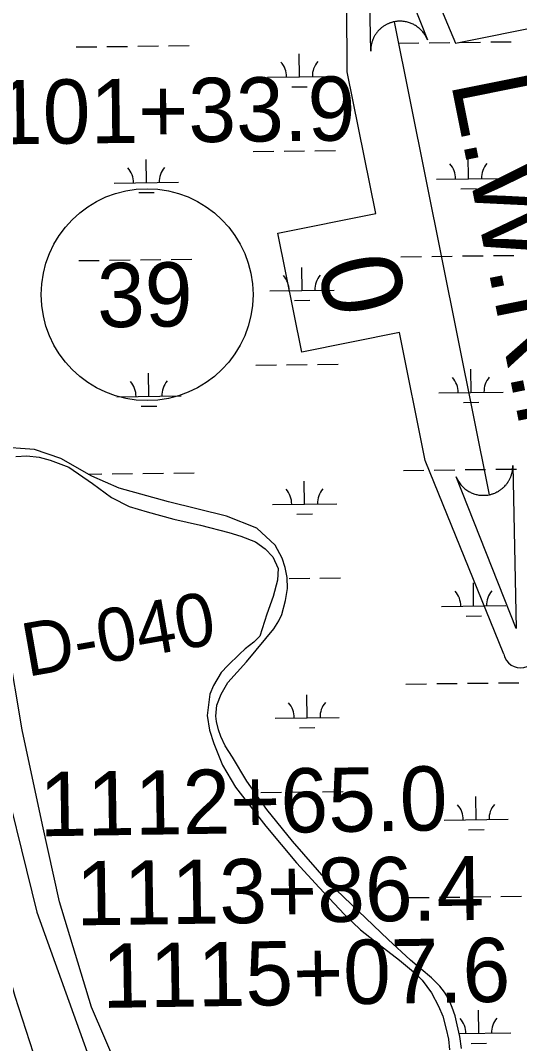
# Model space of a CAD drawing. Extents: x 3694830 to 3732949, y 415201 to 440970.
# Drawn here: x 3719230 to 3720008, y 422124 to 423717 of the extents above; entities that cross this region are included whole.
import ezdxf

# ---------------------------------------------------------------- set-up
doc = ezdxf.new("R2010")
doc.units = 0
for name, color, linetype in [('V-LEVE-TOET', 7, 'Continuous'), ('V-RIVR-EDGE', 7, 'Continuous'), ('V-RIVR-RANG-IDEN', 7, 'Continuous'), ('V-ROAD-CNTR', 7, 'Continuous'), ('V-ROAD-IDEN', 7, 'Continuous'), ('V-SITE-VEGE', 7, 'Continuous'), ('V-SURV-IDEN', 7, 'Continuous'), ('V-TOPO-WATR-IDEN', 7, 'Continuous'), ('V-WETL-SWMP', 7, 'Continuous')]:
    doc.layers.add(name, color=color, linetype=linetype)

msp = doc.modelspace()

# ---------------------------------------------------------------- linework, layer by layer
at = {"layer": 'V-LEVE-TOET'}
msp.add_lwpolyline([(3719250.8, 422108.8), (3719222.3, 422197), (3719194.8, 422291.7), (3719180.7, 422352.4), (3719172.6, 422421.2), (3719168.1, 422469.1), (3719160.3, 422512), (3719146.7, 422581.8), (3719133.4, 422653.2), (3719118.2, 422780.4)], dxfattribs=at)
at = {"layer": 'V-RIVR-EDGE'}
msp.add_spline([(3719087.8, 422149.1), (3719100.4, 422102), (3719125.5, 422030.5), (3719143.5, 421974.4), (3719160.1, 421927.3), (3719171.7, 421879.4), (3719179.4, 421857.6), (3719191.1, 421841.3), (3719203.2, 421812.4), (3719211.7, 421786.1), (3719228.4, 421748.1), (3719249.5, 421687.5), (3719275.5, 421623.6), (3719294.9, 421574.3), (3719319.2, 421529.5), (3719344.8, 421485.6), (3719365.1, 421454.3), (3719388.1, 421409), (3719408.3, 421361.5), (3719431.6, 421299.1), (3719443.8, 421266.9), (3719451.8, 421214.5), (3719458, 421174.7), (3719470.6, 421133), (3719483.6, 421095.5), (3719507.4, 421024.4), (3719533, 420955.6), (3719560.9, 420891.8), (3719570.8, 420861)], degree=3, dxfattribs=at)
at = {"layer": 'V-ROAD-CNTR'}
msp.add_lwpolyline([(3718947.5, 424793.9), (3718964, 424411.4), (3718982.2, 424062.3), (3719015.2, 423758.3), (3719087.3, 423283.5), (3719154, 422831.8), (3719191.5, 422587.8), (3719255.9, 422328.3), (3719350.6, 422063.9), (3719444.2, 421874.4), (3719568.8, 421676.5), (3719728.1, 421465.7), (3719881.2, 421306.9), (3720024.6, 421178.6), (3720151.9, 421084.4), (3720292.9, 420993.4), (3720460.7, 420905.9), (3720538.9, 420876)], dxfattribs=at)
at = {"layer": 'V-ROAD-IDEN'}
msp.add_circle((3719427.6, 423289.7), 165, dxfattribs=at)
msp.add_circle((3719427.6, 423289.7), 165, dxfattribs=at)
at = {"layer": 'V-SITE-VEGE'}
for p, q in [((3719223.3, 423037.5), (3719240.3, 423038.7)), ((3719240.3, 423038.7), (3719259.2, 423036.7)), ((3719259.2, 423036.7), (3719276.6, 423031.9)), ((3719276.6, 423031.9), (3719305.5, 423020.9)), ((3719305.5, 423020.9), (3719342.6, 422995.6)), ((3719342.6, 422995.6), (3719371.9, 422973.8)), ((3719371.9, 422973.8), (3719399.6, 422959.6)), ((3719399.6, 422959.6), (3719427.6, 422951.6)), ((3719427.6, 422951.6), (3719469.1, 422940.2)), ((3719469.1, 422940.2), (3719511, 422930.7)), ((3719511, 422930.7), (3719554.9, 422919.2)), ((3719554.9, 422919.2), (3719573.5, 422913.6)), ((3719573.5, 422913.6), (3719596.4, 422904.9)), ((3719596.4, 422904.9), (3719611.4, 422893.9)), ((3719611.4, 422893.9), (3719623.7, 422881.6)), ((3719623.7, 422881.6), (3719631.6, 422863.4)), ((3719631.6, 422863.4), (3719630.8, 422845.2)), ((3719630.8, 422845.2), (3719624.1, 422819.9)), ((3719624.1, 422819.9), (3719614.2, 422792.3)), ((3719614.2, 422792.3), (3719603.1, 422757.9)), ((3719603.1, 422757.9), (3719594, 422748.8)), ((3719232.7, 422612.2), (3719210.4, 422744.9)), ((3719594, 422748.8), (3719580.6, 422738.1)), ((3719571.5, 422730), (3719553.3, 422712.4)), ((3719580.6, 422738.1), (3719571.5, 422730)), ((3719553.3, 422712.4), (3719543.1, 422701.1)), ((3719543.1, 422701.1), (3719530.8, 422681.3)), ((3719530.8, 422681.3), (3719525.4, 422667.4)), ((3719525.4, 422667.4), (3719521.1, 422634.2)), ((3719521.1, 422634.2), (3719524.9, 422611.6)), ((3719264.6, 422464), (3719232.7, 422612.2)), ((3719524.9, 422611.6), (3719531.3, 422590.8)), ((3719531.3, 422590.8), (3719545.2, 422557)), ((3719545.2, 422557), (3719565.1, 422522.7)), ((3719565.1, 422522.7), (3719612.7, 422462.2)), ((3719291.2, 422344.3), (3719264.6, 422464)), ((3719612.7, 422462.2), (3719660.4, 422404.8)), ((3719660.4, 422404.8), (3719695.8, 422366.3)), ((3719695.8, 422366.3), (3719734.9, 422324.5)), ((3719341, 422180.3), (3719291.2, 422344.3)), ((3719734.9, 422324.5), (3719760, 422300.9)), ((3719760, 422300.9), (3719789, 422277.9)), ((3719789, 422277.9), (3719820.6, 422253.2)), ((3719820.6, 422253.2), (3719842.5, 422235)), ((3719842.5, 422235), (3719855.9, 422222.1)), ((3719855.9, 422222.1), (3719870.9, 422202.3)), ((3719870.9, 422202.3), (3719881.6, 422182)), ((3719390.5, 422065.8), (3719341, 422180.3)), ((3719881.6, 422182), (3719888.1, 422166.4)), ((3719888.1, 422166.4), (3719893.4, 422146.1)), ((3719893.4, 422146.1), (3719897.2, 422130.5)), ((3719897.2, 422130.5), (3719898.8, 422113.9))]:
    msp.add_line(p, q, dxfattribs=at)
at = {"layer": 'V-TOPO-WATR-IDEN'}
msp.add_line((3719812.7, 423714.6), (3719960.6, 422978.1), dxfattribs=at)
for points in [[(3719983.4, 422729.8), (3719860.9, 423031.4), (3719820.9, 423230.8), (3719668.6, 423200.3), (3719631.4, 423385.6), (3719783.7, 423416.2), (3719739.4, 423636.7), (3719737.9, 423952.5)], [(3719789.9, 423962.9), (3719908.3, 423681.4), (3720050.2, 423709.9), (3720175.9, 423083.8), (3720034, 423055.3), (3720035.4, 422740.2)]]:
    msp.add_lwpolyline(points, dxfattribs=at)
for points in [[(3719776, 423669), (3719770.9, 423922.8), (3719864.2, 423686.7), (3719862.3, 423690.8), (3719860.1, 423694.6), (3719859.1, 423696.1), (3719858.2, 423697.4), (3719857, 423698.9), (3719855.8, 423700.3), (3719854.7, 423701.4), (3719853.2, 423702.9), (3719851.5, 423704.5), (3719850.5, 423705.3), (3719849.1, 423706.4), (3719847.3, 423707.7), (3719845.9, 423708.6), (3719844.3, 423709.5), (3719843.2, 423710.1), (3719842, 423710.7), (3719840.5, 423711.4), (3719839.2, 423712), (3719837.8, 423712.6), (3719836.6, 423713), (3719834.9, 423713.6), (3719833.2, 423714), (3719831.8, 423714.4), (3719830.2, 423714.7), (3719828.8, 423714.9), (3719827.5, 423715.1), (3719826.5, 423715.2), (3719825, 423715.4), (3719823.5, 423715.5), (3719822, 423715.5), (3719820.5, 423715.5), (3719819.2, 423715.4), (3719817.6, 423715.3), (3719816.4, 423715.2), (3719814.7, 423714.9), (3719812.7, 423714.6), (3719812.1, 423714.5), (3719811.2, 423714.3), (3719810.1, 423714), (3719809.1, 423713.7), (3719808.1, 423713.4), (3719807.1, 423713.1), (3719806, 423712.7), (3719805.2, 423712.4), (3719804.1, 423712), (3719803.1, 423711.5), (3719802.4, 423711.2), (3719800.5, 423710.3), (3719799.6, 423709.8), (3719798.9, 423709.4), (3719797.9, 423708.8), (3719797, 423708.2), (3719796, 423707.6), (3719794.9, 423706.8), (3719793.9, 423706.1), (3719793.1, 423705.5), (3719792.5, 423704.9), (3719791.6, 423704.2), (3719790.8, 423703.5), (3719790, 423702.7), (3719789.1, 423701.8), (3719788.3, 423701), (3719787.2, 423699.8), (3719786.5, 423699), (3719785.7, 423698), (3719785, 423697), (3719784.4, 423696.3), (3719783.8, 423695.4), (3719783, 423694.1), (3719782.9, 423694), (3719782.4, 423693.2), (3719782.1, 423692.6), (3719781.6, 423691.7), (3719781, 423690.6), (3719780.5, 423689.7), (3719780.1, 423688.8), (3719779.7, 423687.8), (3719779.2, 423686.7), (3719778.9, 423686), (3719778.6, 423685), (3719778.1, 423683.6), (3719777.9, 423682.7), (3719777.7, 423682.1), (3719777.5, 423681.5), (3719777.3, 423680.8), (3719777.1, 423679.8), (3719776.9, 423678.9), (3719776.7, 423677.9), (3719776.5, 423677), (3719776.4, 423675.7), (3719776.3, 423675), (3719776.1, 423673.8), (3719776, 423672.4), (3719776, 423671.4), (3719776, 423670.6), (3719776, 423669.9), (3719776, 423669.3)], [(3719997.3, 423023.7), (3720002.4, 422769.8), (3719909.1, 423006), (3719911, 423001.9), (3719913.2, 422998), (3719914.2, 422996.6), (3719915.1, 422995.3), (3719916.3, 422993.8), (3719917.5, 422992.4), (3719918.5, 422991.3), (3719920.1, 422989.7), (3719921.8, 422988.2), (3719922.8, 422987.4), (3719924.1, 422986.3), (3719925.9, 422985), (3719927.4, 422984.1), (3719929, 422983.2), (3719930, 422982.6), (3719931.2, 422982), (3719932.7, 422981.3), (3719934.1, 422980.7), (3719935.5, 422980.1), (3719936.7, 422979.7), (3719938.4, 422979.1), (3719940.1, 422978.7), (3719941.5, 422978.3), (3719943.1, 422978), (3719944.5, 422977.7), (3719945.7, 422977.6), (3719946.7, 422977.5), (3719948.2, 422977.3), (3719949.8, 422977.2), (3719951.2, 422977.2), (3719952.7, 422977.2), (3719954.1, 422977.3), (3719955.6, 422977.4), (3719956.9, 422977.5), (3719958.6, 422977.7), (3719960.6, 422978.1), (3719961.2, 422978.2), (3719962.1, 422978.4), (3719963.2, 422978.7), (3719964.2, 422979), (3719965.2, 422979.3), (3719966.1, 422979.6), (3719967.3, 422980), (3719968, 422980.3), (3719969.2, 422980.7), (3719970.2, 422981.2), (3719970.9, 422981.5), (3719972.7, 422982.4), (3719973.7, 422982.9), (3719974.3, 422983.3), (3719975.4, 422983.9), (3719976.3, 422984.5), (3719977.3, 422985.1), (3719978.4, 422985.9), (3719979.4, 422986.6), (3719980.1, 422987.2), (3719980.8, 422987.8), (3719981.7, 422988.5), (3719982.4, 422989.2), (3719983.3, 422990), (3719984.2, 422990.9), (3719985, 422991.7), (3719986, 422992.9), (3719986.8, 422993.7), (3719987.5, 422994.7), (3719988.3, 422995.6), (3719988.8, 422996.4), (3719989.4, 422997.3), (3719990.3, 422998.6), (3719990.3, 422998.7), (3719990.8, 422999.5), (3719991.2, 423000.1), (3719991.7, 423001), (3719992.3, 423002.1), (3719992.7, 423003), (3719993.1, 423003.8), (3719993.6, 423004.9), (3719994, 423006), (3719994.3, 423006.7), (3719994.7, 423007.7), (3719995.2, 423009.1), (3719995.4, 423009.9), (3719995.6, 423010.6), (3719995.8, 423011.2), (3719996, 423011.9), (3719996.2, 423012.9), (3719996.4, 423013.8), (3719996.6, 423014.8), (3719996.7, 423015.7), (3719996.9, 423017), (3719997, 423017.7), (3719997.1, 423018.9), (3719997.2, 423020.3), (3719997.3, 423021.3), (3719997.3, 423022.1), (3719997.3, 423022.8), (3719997.3, 423023.3)]]:
    msp.add_lwpolyline(points, close=True, dxfattribs=at)
msp.add_arc((3720009.4, 422735), 26.5, 191.3511, 11.3511, dxfattribs=at)
at = {"layer": 'V-WETL-SWMP'}
for p, q in [((3719819, 423681.4), (3719851, 423681.8)), ((3719867, 423681.9), (3719899, 423682.3)), ((3719915, 423682.5), (3719947, 423682.9)), ((3719963, 423683.1), (3719995, 423683.5)), ((3719317.1, 423675.4), (3719349.1, 423675.8)), ((3719365.1, 423676), (3719397.1, 423676.3)), ((3719413.1, 423676.5), (3719445.1, 423676.9)), ((3719461.1, 423677.1), (3719493.1, 423677.5)), ((3719665, 423628.8), (3719664.6, 423664.8)), ((3719615, 423628.2), (3719715, 423629.4)), ((3719653.2, 423613.2), (3719677.2, 423613.5)), ((3719593, 423512.5), (3719625, 423512.9)), ((3719641, 423513.1), (3719673, 423513.4)), ((3719689, 423513.6), (3719721, 423514)), ((3719928.4, 423470.1), (3719927.9, 423506.1)), ((3719426.5, 423464.1), (3719426.1, 423500.1)), ((3719376.5, 423463.5), (3719476.5, 423464.7)), ((3719878.4, 423469.5), (3719978.4, 423470.7)), ((3719414.7, 423448.5), (3719438.7, 423448.8)), ((3719916.6, 423454.5), (3719940.6, 423454.8)), ((3719823, 423348.7), (3719855, 423349.1)), ((3719871, 423349.3), (3719903, 423349.7)), ((3719919, 423349.9), (3719951, 423350.3)), ((3719967, 423350.4), (3719999, 423350.8)), ((3719321.1, 423342.7), (3719353.1, 423343.1)), ((3719369.1, 423343.3), (3719401.1, 423343.7)), ((3719417.1, 423343.9), (3719449.1, 423344.3)), ((3719465.1, 423344.5), (3719497.1, 423344.8)), ((3719669, 423296.1), (3719668.6, 423332.1)), ((3719619, 423295.5), (3719719, 423296.7)), ((3719657.2, 423280.6), (3719681.2, 423280.9)), ((3719597, 423179.8), (3719629, 423180.2)), ((3719645, 423180.4), (3719677, 423180.8)), ((3719693, 423181), (3719725, 423181.4)), ((3719932.3, 423137.4), (3719931.9, 423173.4)), ((3719430.5, 423131.4), (3719430, 423167.4)), ((3719380.5, 423130.8), (3719480.5, 423132)), ((3719882.3, 423136.8), (3719982.3, 423138)), ((3719418.6, 423115.9), (3719442.6, 423116.1)), ((3719920.5, 423121.8), (3719944.5, 423122.1)), ((3719252.4, 423048.6), (3719192.3, 423052.9)), ((3719293.1, 423034.3), (3719252.4, 423048.6)), ((3719341.3, 423007), (3719293.1, 423034.3)), ((3719469, 423011.8), (3719501, 423012.2)), ((3719826.9, 423016.1), (3719858.9, 423016.5)), ((3719874.9, 423016.6), (3719906.9, 423017)), ((3719922.9, 423017.2), (3719954.9, 423017.6)), ((3719970.9, 423017.8), (3720002.9, 423018.2)), ((3719335.7, 423010.2), (3719357.1, 423010.5)), ((3719384, 422988.4), (3719341.3, 423007)), ((3719373.1, 423010.7), (3719405.1, 423011)), ((3719421.1, 423011.2), (3719453.1, 423011.6)), ((3719673, 422963.5), (3719672.5, 422999.5)), ((3719461.1, 422967), (3719384, 422988.4)), ((3719551.2, 422944.9), (3719461.1, 422967)), ((3719623, 422962.9), (3719723, 422964.1)), ((3719661.1, 422947.9), (3719685.1, 422948.2)), ((3719598.3, 422925.9), (3719551.2, 422944.9)), ((3719627.1, 422899.4), (3719598.3, 422925.9)), ((3719638.2, 422879.2), (3719627.1, 422899.4)), ((3719642.5, 422865), (3719638.2, 422879.2)), ((3719645.7, 422849.2), (3719642.5, 422865)), ((3719646.1, 422832.2), (3719645.7, 422849.2)), ((3719648.9, 422847.8), (3719680.9, 422848.1)), ((3719696.9, 422848.3), (3719728.9, 422848.7)), ((3719936.3, 422804.8), (3719935.9, 422840.8)), ((3719643.3, 422813.2), (3719646.1, 422832.2)), ((3719637.4, 422791.4), (3719643.3, 422813.2)), ((3719886.3, 422804.2), (3719986.3, 422805.4)), ((3719633, 422782), (3719637.4, 422791.4)), ((3719924.5, 422789.2), (3719948.5, 422789.5)), ((3719625.1, 422769.3), (3719633, 422782)), ((3719612.8, 422754.3), (3719625.1, 422769.3)), ((3719582.3, 422718.1), (3719612.8, 422754.3)), ((3719553.6, 422685.7), (3719582.3, 422718.1)), ((3719543.1, 422667.8), (3719553.6, 422685.7)), ((3719830.9, 422683.4), (3719862.9, 422683.8)), ((3719878.9, 422684), (3719910.9, 422684.4)), ((3719926.9, 422684.6), (3719958.9, 422684.9)), ((3719974.9, 422685.1), (3720006.9, 422685.5)), ((3719536.4, 422650.5), (3719543.1, 422667.8)), ((3719676.9, 422630.8), (3719676.5, 422666.8)), ((3719534.5, 422633.2), (3719536.4, 422650.5)), ((3719535.5, 422625.1), (3719534.5, 422633.2)), ((3719626.9, 422630.2), (3719726.9, 422631.4)), ((3719538.8, 422612.2), (3719535.5, 422625.1)), ((3719665.1, 422615.3), (3719689.1, 422615.6)), ((3719542.6, 422601.6), (3719538.8, 422612.2)), ((3719549.3, 422587.3), (3719542.6, 422601.6)), ((3719560.4, 422569.5), (3719549.3, 422587.3)), ((3719582.8, 422531.9), (3719560.4, 422569.5)), ((3719614.2, 422488.1), (3719582.8, 422531.9)), ((3719604.9, 422514.5), (3719636.9, 422514.9)), ((3719652.9, 422515.1), (3719684.9, 422515.5)), ((3719700.9, 422515.7), (3719732.9, 422516.1)), ((3719940.3, 422472.1), (3719939.8, 422508.1)), ((3719653.9, 422438.9), (3719614.2, 422488.1)), ((3719890.3, 422471.5), (3719990.3, 422472.7)), ((3719928.5, 422456.5), (3719952.5, 422456.8)), ((3719710.6, 422373.8), (3719653.9, 422438.9)), ((3719803, 422285.5), (3719710.6, 422373.8)), ((3719834.9, 422350.8), (3719866.9, 422351.2)), ((3719882.9, 422351.3), (3719914.9, 422351.7)), ((3719930.9, 422351.9), (3719962.9, 422352.3)), ((3719978.9, 422352.5), (3720010.9, 422352.9)), ((3719837.9, 422253.3), (3719803, 422285.5)), ((3719854.6, 422239.2), (3719837.9, 422253.3)), ((3719870.8, 422226), (3719854.6, 422239.2)), ((3719883.5, 422213), (3719870.8, 422226)), ((3719891.1, 422203.8), (3719883.5, 422213)), ((3719897.3, 422193.8), (3719891.1, 422203.8)), ((3719903, 422179.5), (3719897.3, 422193.8)), ((3719907.3, 422166.5), (3719903, 422179.5)), ((3719944.2, 422139.5), (3719943.8, 422175.5)), ((3719910.8, 422152.8), (3719907.3, 422166.5)), ((3719914.6, 422134.7), (3719910.8, 422152.8)), ((3719913.7, 422139.1), (3719994.2, 422140.1)), ((3719917.3, 422115.7), (3719914.6, 422134.7)), ((3719932.4, 422123.9), (3719956.4, 422124.2))]:
    msp.add_line(p, q, dxfattribs=at)
for centre, start, end in [((3719609.8, 423628.6), 359.9115, 41.4552), ((3719720.3, 423629.9), 139.9115, 181.4552), ((3719873.1, 423469.9), 359.9115, 41.4552), ((3719983.6, 423471.2), 139.9115, 181.4552), ((3719371.3, 423463.9), 359.9115, 41.4552), ((3719481.7, 423465.2), 139.9115, 181.4552), ((3719613.7, 423296), 359.9115, 41.4552), ((3719724.2, 423297.3), 139.9115, 181.4552), ((3719485.7, 423132.6), 139.9115, 181.4552), ((3719877.1, 423137.2), 359.9115, 41.4552), ((3719987.6, 423138.5), 139.9115, 181.4552), ((3719375.2, 423131.2), 359.9115, 41.4552), ((3719617.7, 422963.3), 359.9115, 41.4552), ((3719728.2, 422964.6), 139.9115, 181.4552), ((3719881.1, 422804.6), 359.9115, 41.4552), ((3719991.5, 422805.9), 139.9115, 181.4552), ((3719621.7, 422630.7), 359.9115, 41.4552), ((3719732.2, 422632), 139.9115, 181.4552), ((3719885, 422471.9), 359.9115, 41.4552), ((3719995.5, 422473.2), 139.9115, 181.4552), ((3719889, 422139.3), 359.9115, 41.4552), ((3719999.5, 422140.6), 139.9115, 181.4552)]:
    msp.add_arc(centre, 35.2, start, end, dxfattribs=at)

# ---------------------------------------------------------------- texts
at = {"layer": 'V-RIVR-RANG-IDEN'}
msp.add_text('D-040', height=83, rotation=9.9483, dxfattribs=at).set_placement((3719240.9, 422694.5))
at = {"layer": 'V-ROAD-IDEN'}
msp.add_text('39', height=100, rotation=0.6667, dxfattribs=at).set_placement((3719350.2, 423238.7))
at = {"layer": 'V-SURV-IDEN'}
for s, rotation, p in [('1101+33.9', 0.6305, (3719116.7, 423522.8)), ('1112+65.0', 0.8588, (3719260.4, 422446.2)), ('1113+86.4', 0.7704, (3719317.5, 422307.5)), ('1115+07.6', 0.8805, (3719358.2, 422179))]:
    msp.add_text(s, height=100, rotation=rotation, dxfattribs=at).set_placement(p)
at = {"layer": 'V-TOPO-WATR-IDEN'}
for s, rotation, p in [('L.W.R.P.', 281.351, (3719900.4, 423620.9)), ('0', 281.3511, (3719692.3, 423339))]:
    msp.add_text(s, height=124.5, rotation=rotation, dxfattribs=at).set_placement(p)

doc.saveas('drawing.dxf')
